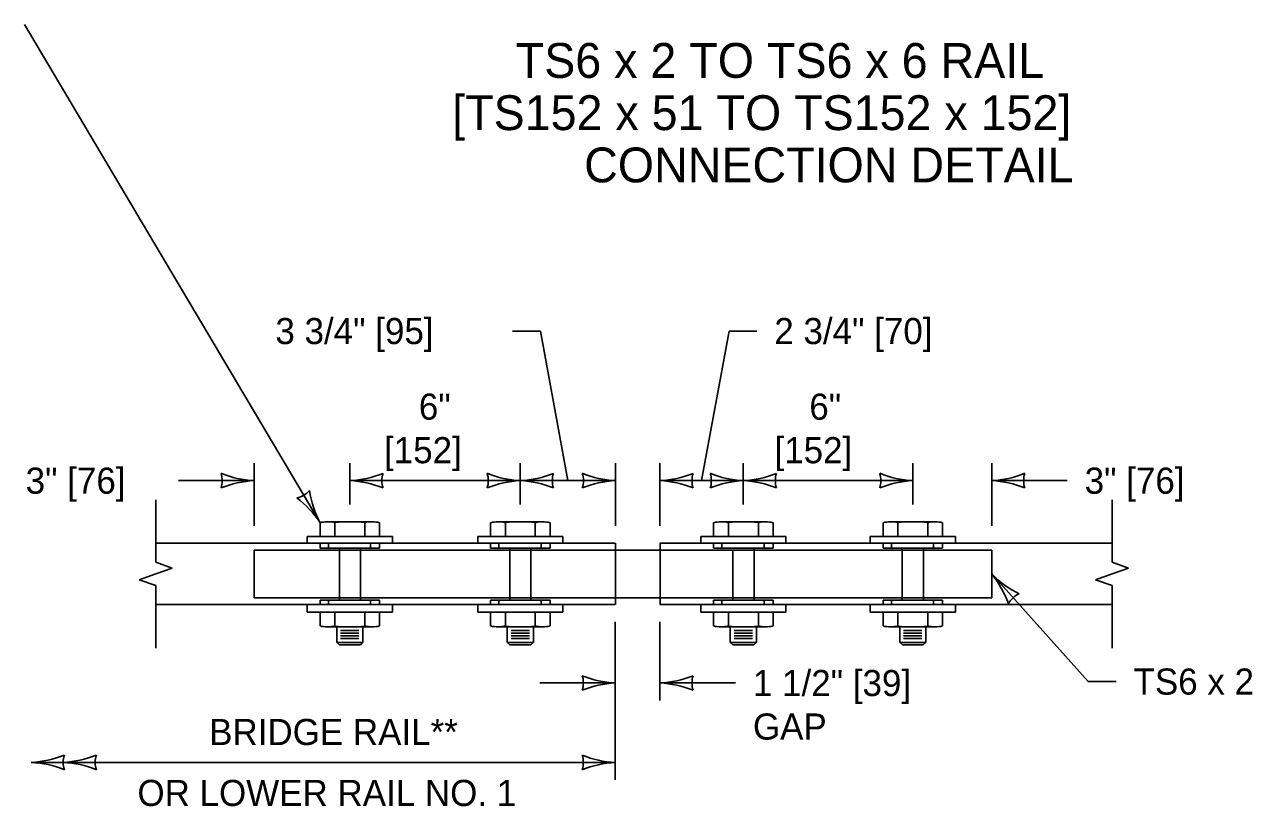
# Model space of a CAD drawing. Extents: x 49991.4 to 50021, y 49987.6 to 50011.4.
# Drawn here: x 50011.512 to 50014.342, y 49991.74 to 49993.536 of the extents above; entities that cross this region are included whole.
import ezdxf

# ---------------------------------------------------------------- set-up
doc = ezdxf.new("R2010")
doc.units = 0
for name, color, linetype in [('Level 1', 7, 'Continuous'), ('Level 2', 7, 'Continuous'), ('Level 3', 7, 'Continuous'), ('Level 4', 7, 'Continuous'), ('Level 6', 7, 'Continuous')]:
    doc.layers.add(name, color=color, linetype=linetype)

msp = doc.modelspace()

# ---------------------------------------------------------------- linework, layer by layer
at = {"layer": 'Level 1'}
for p, q in [((50012.1906, 49992.3918), (50012.1906, 49992.36)), ((50012.2077, 49992.3939), (50012.3098, 49992.3939)), ((50012.2244, 49992.3918), (50012.2244, 49992.3601)), ((50012.2932, 49992.3918), (50012.2932, 49992.3601)), ((50012.327, 49992.3918), (50012.327, 49992.36)), ((50012.5818, 49992.3918), (50012.5818, 49992.36)), ((50012.5989, 49992.3939), (50012.701, 49992.3939)), ((50012.6156, 49992.3918), (50012.6156, 49992.3601)), ((50012.6844, 49992.3918), (50012.6844, 49992.3601)), ((50012.7182, 49992.3918), (50012.7182, 49992.36)), ((50013.0937, 49992.3918), (50013.0937, 49992.36)), ((50013.1108, 49992.3939), (50013.2129, 49992.3939)), ((50013.1275, 49992.3918), (50013.1275, 49992.3601)), ((50013.1963, 49992.3918), (50013.1963, 49992.3601)), ((50013.2301, 49992.3918), (50013.2301, 49992.36)), ((50013.4828, 49992.3918), (50013.4828, 49992.36)), ((50013.4999, 49992.3939), (50013.602, 49992.3939)), ((50013.5166, 49992.3918), (50013.5166, 49992.3601)), ((50013.5854, 49992.3918), (50013.5854, 49992.3601)), ((50013.6192, 49992.3918), (50013.6192, 49992.36)), ((50012.3565, 49992.36), (50012.1611, 49992.36)), ((50012.1611, 49992.3445), (50012.1611, 49992.36)), ((50012.1906, 49992.36), (50012.327, 49992.36)), ((50012.3565, 49992.3445), (50012.3565, 49992.36)), ((50012.7477, 49992.36), (50012.5523, 49992.36)), ((50012.5523, 49992.3445), (50012.5523, 49992.36)), ((50012.5818, 49992.36), (50012.7182, 49992.36)), ((50012.7477, 49992.3445), (50012.7477, 49992.36)), ((50013.2596, 49992.36), (50013.0642, 49992.36)), ((50013.0642, 49992.3445), (50013.0642, 49992.36)), ((50013.0937, 49992.36), (50013.2301, 49992.36)), ((50013.2596, 49992.3445), (50013.2596, 49992.36)), ((50013.6487, 49992.36), (50013.4533, 49992.36)), ((50013.4533, 49992.3445), (50013.4533, 49992.36)), ((50013.4828, 49992.36), (50013.6192, 49992.36)), ((50013.6487, 49992.3445), (50013.6487, 49992.36)), ((50011.8133, 49992.3444), (50012.8678, 49992.3444)), ((50012.8683, 49992.3445), (50012.8683, 49992.2038)), ((50012.8683, 49992.3289), (50012.9708, 49992.3289)), ((50012.9704, 49992.3444), (50014.0083, 49992.3444)), ((50012.9708, 49992.3445), (50012.9708, 49992.2038)), ((50012.8683, 49992.2191), (50012.9708, 49992.2191)), ((50011.8133, 49992.2038), (50012.8678, 49992.2038)), ((50012.1611, 49992.2038), (50012.1611, 49992.1864)), ((50012.3565, 49992.1864), (50012.1611, 49992.1864)), ((50012.327, 49992.1864), (50012.1906, 49992.1864)), ((50012.1906, 49992.1546), (50012.1906, 49992.1864)), ((50012.2244, 49992.1545), (50012.2244, 49992.1863)), ((50012.2932, 49992.1545), (50012.2932, 49992.1863)), ((50012.327, 49992.1546), (50012.327, 49992.1864)), ((50012.3565, 49992.2038), (50012.3565, 49992.1864)), ((50012.5523, 49992.2038), (50012.5523, 49992.1864)), ((50012.7477, 49992.1864), (50012.5523, 49992.1864)), ((50012.7182, 49992.1864), (50012.5818, 49992.1864)), ((50012.5818, 49992.1546), (50012.5818, 49992.1864)), ((50012.6156, 49992.1545), (50012.6156, 49992.1863)), ((50012.6844, 49992.1545), (50012.6844, 49992.1863)), ((50012.7182, 49992.1546), (50012.7182, 49992.1864)), ((50012.7477, 49992.2038), (50012.7477, 49992.1864)), ((50012.9704, 49992.2038), (50014.0083, 49992.2038)), ((50013.0642, 49992.2038), (50013.0642, 49992.1864)), ((50013.2596, 49992.1864), (50013.0642, 49992.1864)), ((50013.2301, 49992.1864), (50013.0937, 49992.1864)), ((50013.0937, 49992.1546), (50013.0937, 49992.1864)), ((50013.1275, 49992.1545), (50013.1275, 49992.1863)), ((50013.1963, 49992.1545), (50013.1963, 49992.1863)), ((50013.2301, 49992.1546), (50013.2301, 49992.1864)), ((50013.2596, 49992.2038), (50013.2596, 49992.1864)), ((50013.4533, 49992.2038), (50013.4533, 49992.1864)), ((50013.6487, 49992.1864), (50013.4533, 49992.1864)), ((50013.6192, 49992.1864), (50013.4828, 49992.1864)), ((50013.4828, 49992.1546), (50013.4828, 49992.1864)), ((50013.5166, 49992.1545), (50013.5166, 49992.1863)), ((50013.5854, 49992.1545), (50013.5854, 49992.1863)), ((50013.6192, 49992.1546), (50013.6192, 49992.1864)), ((50013.6487, 49992.2038), (50013.6487, 49992.1864)), ((50012.3099, 49992.1525), (50012.2078, 49992.1525)), ((50012.2288, 49992.1169), (50012.2288, 49992.1524)), ((50012.2376, 49992.1441), (50012.2797, 49992.1441)), ((50012.2376, 49992.1381), (50012.2797, 49992.1381)), ((50012.2376, 49992.1321), (50012.2797, 49992.1321)), ((50012.2888, 49992.1169), (50012.2888, 49992.1524)), ((50012.7011, 49992.1525), (50012.599, 49992.1525)), ((50012.62, 49992.1169), (50012.62, 49992.1524)), ((50012.6288, 49992.1441), (50012.6709, 49992.1441)), ((50012.6288, 49992.1381), (50012.6709, 49992.1381)), ((50012.6288, 49992.1321), (50012.6709, 49992.1321)), ((50012.68, 49992.1169), (50012.68, 49992.1524)), ((50013.213, 49992.1525), (50013.1109, 49992.1525)), ((50013.1319, 49992.1169), (50013.1319, 49992.1524)), ((50013.1407, 49992.1441), (50013.1828, 49992.1441)), ((50013.1407, 49992.1381), (50013.1828, 49992.1381)), ((50013.1407, 49992.1321), (50013.1828, 49992.1321)), ((50013.1919, 49992.1169), (50013.1919, 49992.1524)), ((50013.6021, 49992.1525), (50013.5, 49992.1525)), ((50013.521, 49992.1169), (50013.521, 49992.1524)), ((50013.5298, 49992.1441), (50013.5719, 49992.1441)), ((50013.5298, 49992.1381), (50013.5719, 49992.1381)), ((50013.5298, 49992.1321), (50013.5719, 49992.1321)), ((50013.581, 49992.1169), (50013.581, 49992.1524)), ((50012.2888, 49992.1169), (50012.2288, 49992.1169)), ((50012.2289, 49992.117), (50012.2349, 49992.111)), ((50012.2349, 49992.111), (50012.2828, 49992.111)), ((50012.2376, 49992.1261), (50012.2797, 49992.1261)), ((50012.2887, 49992.117), (50012.2828, 49992.111)), ((50012.68, 49992.1169), (50012.62, 49992.1169)), ((50012.6201, 49992.117), (50012.6261, 49992.111)), ((50012.6261, 49992.111), (50012.674, 49992.111)), ((50012.6288, 49992.1261), (50012.6709, 49992.1261)), ((50012.6799, 49992.117), (50012.674, 49992.111)), ((50013.1919, 49992.1169), (50013.1319, 49992.1169)), ((50013.132, 49992.117), (50013.138, 49992.111)), ((50013.138, 49992.111), (50013.1859, 49992.111)), ((50013.1407, 49992.1261), (50013.1828, 49992.1261)), ((50013.1918, 49992.117), (50013.1859, 49992.111)), ((50013.581, 49992.1169), (50013.521, 49992.1169)), ((50013.5211, 49992.117), (50013.5271, 49992.111)), ((50013.5271, 49992.111), (50013.575, 49992.111)), ((50013.5298, 49992.1261), (50013.5719, 49992.1261)), ((50013.5809, 49992.117), (50013.575, 49992.111))]:
    msp.add_line(p, q, dxfattribs=at)
for centre, major_axis, start_param, end_param in [((50012.2076, 49992.3778), (0.0341, 0), 1.056847, 2.094396), ((50012.2588, 49992.3296), (0.1365, 0), 1.315951, 1.825641), ((50012.31, 49992.3778), (0.0341, 0), 1.047198, 2.084746), ((50012.5988, 49992.3778), (0.0341, 0), 1.056847, 2.094396), ((50012.65, 49992.3296), (0.1365, 0), 1.315951, 1.825641), ((50012.7012, 49992.3778), (0.0341, 0), 1.047198, 2.084746), ((50013.1107, 49992.3778), (0.0341, 0), 1.056847, 2.094396), ((50013.1619, 49992.3296), (0.1365, 0), 1.315951, 1.825641), ((50013.2131, 49992.3778), (0.0341, 0), 1.047198, 2.084746), ((50013.4998, 49992.3778), (0.0341, 0), 1.056847, 2.094396), ((50013.551, 49992.3296), (0.1365, 0), 1.315951, 1.825641), ((50013.6022, 49992.3778), (0.0341, 0), 1.047198, 2.084746), ((50012.2076, 49992.1686), (-0.0341, 0), 1.047198, 2.084746), ((50012.2588, 49992.2168), (-0.1365, 0), 1.315951, 1.825641), ((50012.31, 49992.1686), (-0.0341, 0), 1.056847, 2.094396), ((50012.5988, 49992.1686), (-0.0341, 0), 1.047198, 2.084746), ((50012.65, 49992.2168), (-0.1365, 0), 1.315951, 1.825641), ((50012.7012, 49992.1686), (-0.0341, 0), 1.056847, 2.094396), ((50013.1107, 49992.1686), (-0.0341, 0), 1.047198, 2.084746), ((50013.1619, 49992.2168), (-0.1365, 0), 1.315951, 1.825641), ((50013.2131, 49992.1686), (-0.0341, 0), 1.056847, 2.094396), ((50013.4998, 49992.1686), (-0.0341, 0), 1.047198, 2.084746), ((50013.551, 49992.2168), (-0.1365, 0), 1.315951, 1.825641), ((50013.6022, 49992.1686), (-0.0341, 0), 1.056847, 2.094396)]:
    msp.add_ellipse(centre, major_axis=major_axis, ratio=0.471622, start_param=start_param, end_param=end_param, dxfattribs=at)
at = {"layer": 'Level 3'}
for p, q in [((50012.1906, 49992.3918), (50011.5123, 49993.5356)), ((50012.6323, 49992.8319), (50012.6963, 49992.8319)), ((50013.129, 49992.8319), (50013.193, 49992.8319)), ((50012.0391, 49992.3844), (50012.0391, 49992.5283)), ((50012.2587, 49992.4339), (50012.2587, 49992.5283)), ((50012.6499, 49992.4339), (50012.6499, 49992.5283)), ((50012.8683, 49992.3844), (50012.8683, 49992.5283)), ((50012.9704, 49992.3844), (50012.9704, 49992.5283)), ((50013.1618, 49992.4339), (50013.1618, 49992.5283)), ((50013.5509, 49992.4339), (50013.5509, 49992.5283)), ((50013.7319, 49992.3844), (50013.7319, 49992.5283)), ((50012.0391, 49992.4883), (50011.8657, 49992.4883)), ((50012.2587, 49992.4883), (50012.6499, 49992.4883)), ((50012.6499, 49992.4883), (50012.8683, 49992.4883)), ((50013.1618, 49992.4883), (50012.9704, 49992.4883)), ((50013.1502, 49992.4883), (50013.5509, 49992.4883)), ((50013.7319, 49992.4883), (50013.9053, 49992.4883)), ((50013.7319, 49992.274), (50013.9536, 49992.0269)), ((50012.868, 49991.8012), (50012.868, 49992.1638)), ((50012.9704, 49991.9836), (50012.9704, 49992.1638)), ((50012.868, 49992.0236), (50012.6946, 49992.0236)), ((50013.1439, 49992.0236), (50012.9704, 49992.0236)), ((50013.9536, 49992.0269), (50014.0175, 49992.0269)), ((50012.868, 49991.8412), (50011.5274, 49991.8412))]:
    msp.add_line(p, q, dxfattribs=at)
for points in [[(50012.7591, 49992.4883), (50012.6963, 49992.8319)], [(50013.0661, 49992.4883), (50013.129, 49992.8319)]]:
    msp.add_lwpolyline(points, dxfattribs=at)
for centre, radius, start, end in [((50012.0483, 49992.7105), 0.2223, 247.456, 267.6395), ((50011.9109, 49992.4883), 0.0548, 342.1388, 17.8612), ((50012.2473, 49992.721), 0.233, 272.8273, 292.0772), ((50012.387, 49992.4883), 0.0548, 162.1388, 197.8612), ((50012.6591, 49992.7105), 0.2223, 247.456, 267.6395), ((50012.5217, 49992.4883), 0.0548, 342.1388, 17.8612), ((50012.6385, 49992.721), 0.233, 272.8273, 292.0772), ((50012.7782, 49992.4883), 0.0548, 162.1388, 197.8612), ((50012.8775, 49992.7105), 0.2223, 247.456, 267.6395), ((50012.7401, 49992.4883), 0.0548, 342.1388, 17.8612), ((50012.959, 49992.721), 0.233, 272.8273, 292.0772), ((50013.0987, 49992.4883), 0.0548, 162.1388, 197.8612), ((50013.171, 49992.7105), 0.2223, 247.456, 267.6395), ((50013.0336, 49992.4883), 0.0548, 342.1388, 17.8612), ((50013.1504, 49992.721), 0.233, 272.8273, 292.0772), ((50013.2901, 49992.4883), 0.0548, 162.1388, 197.8612), ((50013.5601, 49992.7105), 0.2223, 247.456, 267.6395), ((50013.4227, 49992.4883), 0.0548, 342.1388, 17.8612), ((50013.7227, 49992.7105), 0.2223, 272.3605, 292.544), ((50013.8601, 49992.4883), 0.0548, 162.1388, 197.8612), ((50012.0506, 49992.2556), 0.233, 92.8273, 112.0772), ((50012.2496, 49992.2662), 0.2223, 67.456, 87.6395), ((50012.6614, 49992.2556), 0.233, 92.8273, 112.0772), ((50012.6408, 49992.2662), 0.2223, 67.456, 87.6395), ((50012.8798, 49992.2556), 0.233, 92.8273, 112.0772), ((50012.9613, 49992.2662), 0.2223, 67.456, 87.6395), ((50013.1733, 49992.2556), 0.233, 92.8273, 112.0772), ((50013.1527, 49992.2662), 0.2223, 67.456, 87.6395), ((50013.5624, 49992.2556), 0.233, 92.8273, 112.0772), ((50013.7204, 49992.2556), 0.233, 67.9228, 87.1727), ((50012.1251, 49992.502), 0.0548, 282.8196, 318.542), ((50011.9963, 49992.2631), 0.233, 33.5081, 52.758), ((50012.3863, 49992.4972), 0.2223, 188.1368, 208.3203), ((50013.8912, 49992.4292), 0.2223, 224.2462, 244.4297), ((50013.551, 49992.1272), 0.233, 19.8085, 39.0584), ((50013.8175, 49992.1786), 0.0548, 114.0245, 149.7469), ((50012.8771, 49992.2457), 0.2223, 247.456, 267.6395), ((50012.7398, 49992.0236), 0.0548, 342.1388, 17.8612), ((50012.8795, 49991.7909), 0.233, 92.8273, 112.0772), ((50012.9589, 49992.2563), 0.233, 272.8273, 292.0772), ((50012.9613, 49991.8015), 0.2223, 67.456, 87.6395), ((50013.0987, 49992.0236), 0.0548, 162.1388, 197.8612), ((50011.5159, 49992.0739), 0.233, 272.8273, 292.0772), ((50011.5894, 49992.0739), 0.233, 272.8273, 292.0772), ((50011.6556, 49991.8412), 0.0548, 162.1388, 197.8612), ((50011.7291, 49991.8412), 0.0548, 162.1388, 197.8612), ((50012.8771, 49992.0633), 0.2223, 247.456, 267.6395), ((50012.7398, 49991.8412), 0.0548, 342.1388, 17.8612), ((50011.5183, 49991.619), 0.2223, 67.456, 87.6395), ((50011.5917, 49991.619), 0.2223, 67.456, 87.6395), ((50012.8795, 49991.6085), 0.233, 92.8273, 112.0772)]:
    msp.add_arc(centre, radius, start, end, dxfattribs=at)
at = {"layer": 'Level 4'}
for p, q in [((50012.0391, 49992.2191), (50012.0391, 49992.3289)), ((50012.0391, 49992.3289), (50012.8683, 49992.3289)), ((50012.1905, 49992.3335), (50012.1905, 49992.3445)), ((50012.327, 49992.3335), (50012.1905, 49992.3335)), ((50012.2098, 49992.3335), (50012.2098, 49992.3445)), ((50012.2346, 49992.3335), (50012.2346, 49992.2138)), ((50012.2833, 49992.3335), (50012.2833, 49992.2138)), ((50012.3064, 49992.3335), (50012.3064, 49992.3445)), ((50012.327, 49992.3335), (50012.327, 49992.3445)), ((50012.5817, 49992.3335), (50012.5817, 49992.3445)), ((50012.7182, 49992.3335), (50012.5817, 49992.3335)), ((50012.601, 49992.3335), (50012.601, 49992.3445)), ((50012.6258, 49992.3335), (50012.6258, 49992.2138)), ((50012.6745, 49992.3335), (50012.6745, 49992.2138)), ((50012.6976, 49992.3335), (50012.6976, 49992.3445)), ((50012.7182, 49992.3335), (50012.7182, 49992.3445)), ((50012.9708, 49992.3289), (50013.7319, 49992.3289)), ((50013.0936, 49992.3335), (50013.0936, 49992.3445)), ((50013.2301, 49992.3335), (50013.0936, 49992.3335)), ((50013.1129, 49992.3335), (50013.1129, 49992.3445)), ((50013.1377, 49992.3289), (50013.1377, 49992.2138)), ((50013.1864, 49992.3335), (50013.1864, 49992.2138)), ((50013.2095, 49992.3335), (50013.2095, 49992.3445)), ((50013.2301, 49992.3335), (50013.2301, 49992.3445)), ((50013.4827, 49992.3335), (50013.4827, 49992.3445)), ((50013.6192, 49992.3335), (50013.4827, 49992.3335)), ((50013.502, 49992.3335), (50013.502, 49992.3445)), ((50013.5268, 49992.3335), (50013.5268, 49992.2138)), ((50013.5755, 49992.3335), (50013.5755, 49992.2138)), ((50013.5986, 49992.3335), (50013.5986, 49992.3445)), ((50013.6192, 49992.3335), (50013.6192, 49992.3445)), ((50013.7319, 49992.3289), (50013.7319, 49992.2191)), ((50012.0391, 49992.2191), (50012.8683, 49992.2191)), ((50012.327, 49992.2138), (50012.1905, 49992.2138)), ((50012.1905, 49992.2138), (50012.1905, 49992.2038)), ((50012.2098, 49992.2138), (50012.2098, 49992.2038)), ((50012.3064, 49992.2138), (50012.3064, 49992.2038)), ((50012.327, 49992.2138), (50012.327, 49992.2038)), ((50012.7182, 49992.2138), (50012.5817, 49992.2138)), ((50012.5817, 49992.2138), (50012.5817, 49992.2038)), ((50012.601, 49992.2138), (50012.601, 49992.2038)), ((50012.6976, 49992.2138), (50012.6976, 49992.2038)), ((50012.7182, 49992.2138), (50012.7182, 49992.2038)), ((50012.9708, 49992.2191), (50013.7319, 49992.2191)), ((50013.2301, 49992.2138), (50013.0936, 49992.2138)), ((50013.0936, 49992.2138), (50013.0936, 49992.2038)), ((50013.1129, 49992.2138), (50013.1129, 49992.2038)), ((50013.2095, 49992.2138), (50013.2095, 49992.2038)), ((50013.2301, 49992.2138), (50013.2301, 49992.2038)), ((50013.6192, 49992.2138), (50013.4827, 49992.2138)), ((50013.4827, 49992.2138), (50013.4827, 49992.2038)), ((50013.502, 49992.2138), (50013.502, 49992.2038)), ((50013.5986, 49992.2138), (50013.5986, 49992.2038)), ((50013.6192, 49992.2138), (50013.6192, 49992.2038))]:
    msp.add_line(p, q, dxfattribs=at)
at = {"layer": 'Level 6'}
for p, q in [((50011.8133, 49992.4444), (50011.8133, 49992.3009)), ((50014.0083, 49992.4444), (50014.0083, 49992.3009)), ((50011.8512, 49992.2876), (50011.8133, 49992.3009)), ((50014.0462, 49992.2876), (50014.0083, 49992.3009)), ((50011.8133, 49992.2741), (50011.7754, 49992.2606)), ((50011.8512, 49992.2876), (50011.8133, 49992.2741)), ((50014.0083, 49992.2741), (50013.9704, 49992.2606)), ((50014.0462, 49992.2876), (50014.0083, 49992.2741)), ((50011.8133, 49992.2473), (50011.7754, 49992.2606)), ((50011.8133, 49992.2473), (50011.8133, 49992.1038)), ((50014.0083, 49992.2473), (50013.9704, 49992.2606)), ((50014.0083, 49992.2473), (50014.0083, 49992.1038))]:
    msp.add_line(p, q, dxfattribs=at)

# ---------------------------------------------------------------- texts
at = {"layer": 'Level 2'}
for s, height, p in [('TS6 x 2 TO TS6 x 6 RAIL ', 0.08, (50012.6395, 49993.4134)), ('[TS152 x 51 TO TS152 x 152]', 0.08, (50012.4936, 49993.2934)), ('CONNECTION DETAIL', 0.08, (50012.7965, 49993.1734)), ('3 3/4" [95]', 0.06, (50012.0878, 49992.8019)), ('2 3/4" [70]', 0.06, (50013.233, 49992.8019)), ('6"', 0.06, (50012.4171, 49992.6283)), ('6"', 0.06, (50013.3133, 49992.6283)), ('[152]', 0.06, (50012.3372, 49992.5283)), ('[152]', 0.06, (50013.2334, 49992.5283)), ('3" [76]', 0.06, (50011.5146, 49992.4583)), ('3" [76]', 0.06, (50013.9453, 49992.4583)), ('1 1/2" [39] ', 0.06, (50013.1839, 49991.9936)), ('TS6 x 2 [TS152 x 51] CONNECTION SLEEVE*', 0.06, (50014.0575, 49991.9969)), ('BRIDGE RAIL**', 0.06, (50011.9358, 49991.8811)), ('GAP', 0.06, (50013.1839, 49991.8936)), ('OR LOWER RAIL NO. 1', 0.06, (50011.7712, 49991.7411))]:
    msp.add_text(s, height=height, dxfattribs=at).set_placement(p)

doc.saveas('drawing.dxf')
